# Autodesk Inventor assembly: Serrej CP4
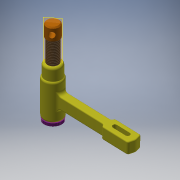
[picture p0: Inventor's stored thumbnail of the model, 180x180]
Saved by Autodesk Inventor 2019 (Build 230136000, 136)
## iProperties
Created: 2019-02
Part Number: Serrej CP4
Material: Générique
Document SubType Name: Assembly
Designer: si-nd67
Author: si-nd67
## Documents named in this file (4)
- E:\ECAM\serrejointsw\Serrej CP4.iam
- E:\ECAM\serrejointsw\Serrej-ACp.iam
- E:\ECAM\serrejointsw\Vis de manoeuvre14.ipt
- E:\ECAM\serrejointsw\Piston14C.ipt
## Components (3 placed, 3 different names)
1. Serrej-ACp:1 [sub-assembly] — Placage:1, 1-Mors-Vis, Angle:1
2. Vis de manoeuvre14:1 — Placage:1, 1-Mors-Vis, Placage:3, Depart vis-piston
3. Piston14C:1 — Placage:3, Angle:1, Depart vis-piston
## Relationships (5: Mate 3, Angle 1, Flush 1)
- Placage:1 [Mate]: Serrej-ACp:1 ↔ Vis de manoeuvre14:1
- 1-Mors-Vis [Mate]: Serrej-ACp:1 ↔ Vis de manoeuvre14:1
- Placage:3 [Mate]: Vis de manoeuvre14:1 ↔ Piston14C:1
- Angle:1: Serrej-ACp:1 ↔ Piston14C:1
- Depart vis-piston [Flush]: Vis de manoeuvre14:1 ↔ Piston14C:1
